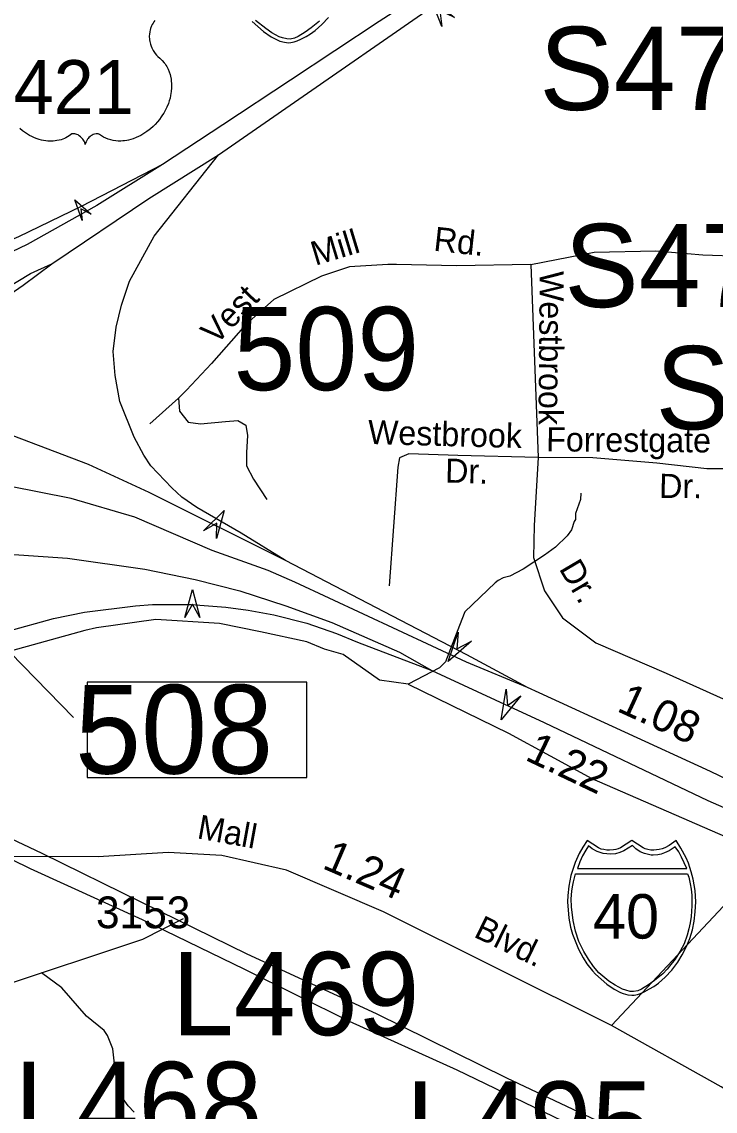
# Model space of a CAD drawing. Extents: x 1547597 to 1699558, y 810033 to 920809.
# Drawn here: x 1609043 to 1611776, y 845095 to 849388 of the extents above; entities that cross this region are included whole.
import ezdxf

# ---------------------------------------------------------------- set-up
doc = ezdxf.new("R2010")
doc.units = 0
for name, color, linetype in [('Exist Hydrographic Creek Single Shore', 7, 'Continuous'), ('Exist Hydrographic Misc Water Feature', 7, 'Continuous'), ('Exist Road Non-System Type 51', 7, 'Continuous'), ('Exist Road Non-System Type 51 Label', 7, 'Continuous'), ('Exist Road Primary Interstate Divided Center Attributed', 7, 'Continuous'), ('Exist Road Primary Interstate Mileage Hundredths English Label', 7, 'Continuous'), ('Exist Road Primary Interstate Ramp 1 Lane Attributed', 7, 'Continuous'), ('Exist Road Primary Interstate Shield CELL', 7, 'Continuous'), ('Exist Road Primary Interstate Shield Number Label', 7, 'Continuous'), ('Exist Road Primary Interstate Structure Cantilever Sign Attributed CELL', 7, 'Continuous'), ('Exist Road Primary Interstate Structure Cantilever Sign Number Label', 7, 'Continuous'), ('Exist Road Primary Interstate Structure Ovrhead Sign Attributed CELL', 7, 'Continuous'), ('Exist Road Primary Interstate Structure Ovrhead Sign Number Label', 7, 'Continuous'), ('Exist Road Primary Interstate Structure Standard Bridge Number Label', 7, 'Continuous'), ('Exist Road Primary US Divided Attributed', 7, 'Continuous'), ('Exist Road Primary US Shield CELL', 7, 'Continuous'), ('Exist Road Primary US Shield Number Label', 7, 'Continuous'), ('Exist Road Secondary Mileage Hundredths English Label', 7, 'Continuous'), ('Exist Road Secondary Structure Standard Bridge Number Label', 7, 'Continuous'), ('Exist Road Secondary Type 51 Label', 7, 'Continuous'), ('Exist Road Secondary Type 51 Number Label', 7, 'Continuous'), ('Exist Road Secondary Type 51 Undivided 4 Lane Attributed', 7, 'Continuous'), ('Exist Utilities Electrical Transmission Line', 7, 'Continuous')]:
    doc.layers.add(name, color=color, linetype=linetype)

msp = doc.modelspace()

# ---------------------------------------------------------------- linework, layer by layer
at = {"layer": 'Exist Hydrographic Creek Single Shore'}
for points in [[(1611246.6, 847530), (1611244.3, 847506), (1611225.6, 847450.3), (1611225.1, 847426.3), (1611219.1, 847418.4), (1611208.6, 847386.6), (1611192.3, 847362.8), (1611145.8, 847317.4), (1611103.3, 847286.1), (1611018.7, 847231.3), (1610966.3, 847204), (1610940.2, 847196.4), (1610920.1, 847186.6), (1610907.9, 847176.8), (1610788.9, 847063.2), (1610767.4, 847009.4), (1610712.7, 846865.3), (1610688.4, 846841.7), (1610566, 846777.2)], [(1610566, 846777.2), (1610961, 846584.5), (1611289.6, 846406.6), (1612056.2, 846072.2), (1612287.7, 846369.2), (1612438.7, 846458.1), (1612590.7, 846606), (1612844.7, 846952.1), (1612954.8, 847035.2), (1613264.7, 847173.3)], [(1610566, 846777.2), (1610453, 846793.2), (1610308.9, 846894.9), (1610236.4, 846915.1), (1610166, 846944.4), (1609983.2, 846984), (1609821.8, 847016.3), (1609571.5, 847032.4), (1609336.8, 846999.2), (1609290.9, 846989.4), (1608821.5, 846859.3), (1608481.2, 846771.3), (1607720.5, 846780.1), (1607526.9, 846727.3), (1607190.5, 846575.7), (1607012.5, 846597.3), (1606791.5, 846589.4)], [(1606395.7, 844663.6), (1606562.7, 844719.3), (1606867.7, 845021.6), (1607202.6, 845185.5), (1607520.7, 845297.3), (1607915.7, 845476.4), (1608523.7, 845477.2), (1608941.7, 845580.3), (1609519.7, 845772.1), (1609679.7, 845854.2)]]:
    msp.add_lwpolyline(points, dxfattribs=at)
at = {"layer": 'Exist Hydrographic Misc Water Feature'}
msp.add_lwpolyline([(1609486.3, 845091.1), (1609462.6, 845115.4), (1609439.1, 845147.7), (1609431.3, 845163.9), (1609412.4, 845244.1), (1609401.7, 845340.2), (1609380.5, 845392.5), (1609366.8, 845412.7), (1609297.6, 845469.7), (1609201.2, 845581), (1609120.1, 845639.5)], dxfattribs=at)
at = {"layer": 'Exist Road Non-System Type 51'}
for points in [[(1611048.3, 848432), (1611299.2, 848479.8), (1611542.2, 848485.9), (1611726.7, 848470.5), (1611880.5, 848464.4)], [(1610485.4, 848432), (1610334.7, 848422.8), (1610223.9, 848385.9), (1610036.3, 848293.5), (1609925.6, 848195), (1609790.2, 848041.1), (1609691.8, 847936.4), (1609661, 847905.6)], [(1611048.3, 848432), (1610756.1, 848425.9), (1610519.2, 848432), (1610485.4, 848432)], [(1611048.3, 848432), (1611078, 847671.6)], [(1609661, 847905.6), (1609547.2, 847804.1)], [(1609661, 847905.6), (1609664.1, 847853.3), (1609697.9, 847810.2), (1609747.2, 847804.1), (1609845.6, 847813.3), (1609894.8, 847816.4), (1609925.6, 847797.9), (1609931.7, 847757.9), (1609928.6, 847690.2), (1609928.6, 847637.8), (1609956.3, 847585.5), (1610008.6, 847505.5)], [(1611078, 847671.6), (1610761.5, 847679.1), (1610567.7, 847685.2), (1610530.8, 847669.8), (1610524.6, 847632.9), (1610490.8, 847165)], [(1611078, 847671.6), (1611062.6, 847403.7), (1611059.5, 847277.5), (1611102.6, 847145.2), (1611173.1, 847039.1), (1611305.4, 846940.6), (1611582.2, 846820.5), (1611911.4, 846672.8), (1612215.9, 846565)], [(1611875, 847626.7), (1611742.7, 847626.7), (1611545.8, 847648.3), (1611293.6, 847669.8), (1611078, 847671.6)], [(1611366.8, 845431.8), (1611828.1, 845924.3), (1612061.9, 846181.6)]]:
    msp.add_lwpolyline(points, dxfattribs=at)
at = {"layer": 'Exist Road Primary Interstate Divided Center Attributed'}
for points in [[(1609818, 848863.7), (1610951.8, 849650.5), (1611075.2, 849735.8), (1611208.1, 849832), (1611360.5, 849948.2), (1611508.2, 850064.4), (1611742.4, 850253.5), (1612088.1, 850529.5), (1612330.6, 850725.5)], [(1610880.9, 849686.6), (1610801.9, 849625.3), (1610654, 849520.7), (1610451.7, 849389.8), (1610101.9, 849158.9), (1609835, 848982.1), (1609597.4, 848825.8)], [(1609160.8, 848434.9), (1609543.6, 848692.4), (1609818, 848863.7)], [(1609597.4, 848825.8), (1609338.8, 848663.7), (1609064, 848510.1), (1608755.1, 848363), (1608523.3, 848239.8), (1608398.1, 848184.5), (1608235.8, 848106.3), (1608071.5, 848018.3), (1607971.8, 847958.6)], [(1608507.6, 847894.1), (1608577.1, 847968.7), (1608628.7, 848030.7), (1608682.9, 848079.4), (1608745.7, 848127.1), (1608859.3, 848220), (1609048.4, 848350.8), (1609160.8, 848434.9)], [(1611035.3, 846765.2), (1610795.8, 846864.2), (1610118.6, 847179.8), (1610014, 847225.8), (1609792.5, 847304.8), (1609487.9, 847435.5), (1609237.6, 847509.1), (1608991.2, 847558.7), (1608763.3, 847591.7), (1608603, 847605.2), (1608500.8, 847605.4), (1608391.6, 847601.3), (1608289.9, 847591.6), (1608209.9, 847577)], [(1607391.9, 846999.6), (1607538.3, 847060.1), (1607712.6, 847122.6), (1607907.2, 847179.3), (1608092, 847220.4), (1608274.9, 847254.6), (1608496.9, 847276.6), (1608631.8, 847286.4), (1608854.8, 847292.7), (1608937.9, 847292.7), (1609030.8, 847287.4), (1609223.4, 847273.7), (1609527.5, 847231.1), (1609726, 847190.8), (1609902.5, 847145.8), (1610082.9, 847086.7), (1610264.8, 847021.2), (1610531.7, 846904.5), (1610658.9, 846832.2)], [(1610658.9, 846832.2), (1610961.8, 846690.7), (1611101.2, 846626.2), (1611746, 846318.7), (1612061.9, 846181.6)], [(1612123.7, 846257), (1611757, 846433), (1611081.3, 846743.4), (1611035.3, 846765.2)]]:
    msp.add_lwpolyline(points, dxfattribs=at)
at = {"layer": 'Exist Road Primary Interstate Ramp 1 Lane Attributed'}
for points in [[(1610081.9, 847264.6), (1609906.9, 847372.7), (1609732.4, 847474.4), (1609673.2, 847515), (1609634.6, 847551.1), (1609551.9, 847638.9), (1609523.6, 847680.9), (1609485.5, 847751.3), (1609429.7, 847891.7), (1609411.1, 847994.3), (1609403.3, 848089.2), (1609414.1, 848185), (1609435.6, 848272), (1609467.9, 848365.9), (1609564.7, 848542.9), (1609818, 848863.7)], [(1610081.9, 847264.6), (1609544.6, 847533), (1609305.5, 847643.8), (1608910.9, 847793.1), (1608706.1, 847852.1), (1608604.4, 847878.5), (1608507.6, 847894.1)], [(1611035.3, 846765.2), (1610797.2, 846893.8), (1610081.9, 847264.6)], [(1607391.9, 846999.6), (1607516.1, 846956.1), (1607705.8, 846904.8), (1607792.8, 846883.8), (1607894.5, 846867.1), (1608005, 846856.4), (1608095.4, 846862.5), (1608309.7, 846862.5), (1608500.2, 846879.8), (1608828.4, 846941.2), (1608987.7, 846986.2), (1609167.7, 847036.1), (1609289.9, 847062), (1609490.3, 847086.9), (1609558.3, 847091.3), (1609709.9, 847091.1), (1609846.8, 847080.8), (1609934.3, 847069.8), (1610036.5, 847050.7), (1610166, 847018.7), (1610283.4, 846976.9), (1610365.5, 846943.7), (1610658.9, 846832.2)]]:
    msp.add_lwpolyline(points, dxfattribs=at)
at = {"layer": 'Exist Road Primary Interstate Shield CELL'}
for points in [[(1609950.3, 849389.2), (1609995.1, 849350), (1610025, 849329.6), (1610048.9, 849316.7), (1610060.2, 849312.4), (1610077.8, 849307.5), (1610093.9, 849305.7), (1610103.4, 849306.6), (1610116.1, 849309), (1610128.5, 849313.1), (1610142.6, 849319.3), (1610163.5, 849330.9), (1610180.2, 849340.7), (1610199.6, 849353.7), (1610225.7, 849377.4), (1610251.7, 849404.8)], [(1610215.9, 849390.3), (1610183.6, 849364.4), (1610160.1, 849346.9), (1610132, 849330.2), (1610117.6, 849323.9), (1610101, 849320.4), (1610087.3, 849321.3), (1610070.6, 849325.7), (1610057.2, 849329.4), (1610027.8, 849345.3), (1610003.9, 849361.3), (1609964.1, 849393.9)]]:
    msp.add_lwpolyline(points, dxfattribs=at)
for points in [[(1611446.9, 845551.4), (1611456.3, 845552.3), (1611469.1, 845554.8), (1611481.5, 845558.8), (1611495.6, 845565.1), (1611516.4, 845576.6), (1611533.2, 845586.4), (1611552.5, 845599.4), (1611578.6, 845623.1), (1611604.7, 845650.5), (1611627.7, 845681.6), (1611645.9, 845710.6), (1611662, 845743.7), (1611675.4, 845774.7), (1611686.1, 845810), (1611693.1, 845844.2), (1611696.7, 845879.9), (1611699.1, 845919.5), (1611696.4, 845964), (1611688.7, 846009.6), (1611681.4, 846037.9), (1611670.4, 846071.9), (1611661.4, 846093.6), (1611640.5, 846132), (1611621.8, 846161.6), (1611594.6, 846142.4), (1611576.8, 846133), (1611565.9, 846128.1), (1611554.8, 846125.9), (1611534.3, 846123.5), (1611521.4, 846124), (1611509.5, 846126.7), (1611499.3, 846128.9), (1611491.1, 846133), (1611446.9, 846161.6), (1611402.6, 846133), (1611393.3, 846128.7), (1611383.8, 846126.7), (1611374.6, 846124.2), (1611359.5, 846123.5), (1611347.9, 846123.8), (1611336.1, 846125.9), (1611326.7, 846127.9), (1611316.2, 846133), (1611271.1, 846161.6), (1611253.3, 846135.9), (1611238.9, 846110.5), (1611223.5, 846074.5), (1611214, 846046.7), (1611207.2, 846023.8), (1611198.8, 845981.9), (1611194.5, 845945.3), (1611193.7, 845919.5), (1611198.5, 845855), (1611205.5, 845820.6), (1611212.8, 845792.8), (1611236.6, 845732.8), (1611254.6, 845699.2), (1611270, 845675), (1611291.5, 845647.8), (1611303.2, 845634.9), (1611348, 845595.7), (1611378, 845575.3), (1611401.9, 845562.4), (1611413.1, 845558.1), (1611430.7, 845553.2)], [(1611276.4, 846140.8), (1611265.4, 846123.9), (1611252.8, 846101.1), (1611242.6, 846077.4), (1611232.3, 846051.2), (1611663.8, 846051.1), (1611653.8, 846073.5), (1611643, 846096), (1611631.8, 846116.6), (1611618, 846136.5), (1611593.8, 846121.3), (1611576.2, 846112.9), (1611562, 846108), (1611550.1, 846105.4), (1611531.5, 846103.9), (1611523.1, 846104.4), (1611497.2, 846110.2), (1611479.7, 846117.4), (1611463, 846128.6), (1611449.4, 846141.3), (1611415.2, 846120.6), (1611400.1, 846113.9), (1611382.6, 846109.5), (1611363.5, 846107.1), (1611334.1, 846110.3), (1611311, 846118.2), (1611291.2, 846128.6)], [(1611666.4, 846029.8), (1611671, 846017.6), (1611677.4, 845990.6), (1611680.7, 845969.7), (1611684.1, 845945.7), (1611682.9, 845904.6), (1611680.9, 845862), (1611677, 845836.8), (1611671.8, 845813.9), (1611664.6, 845788.4), (1611653.1, 845754.6), (1611637.2, 845725.9), (1611617.3, 845694.1), (1611595.8, 845666.2), (1611586.5, 845654.7), (1611568.8, 845636), (1611536.6, 845610.1), (1611513.1, 845592.6), (1611484.9, 845575.9), (1611470.6, 845569.6), (1611453.9, 845566.1), (1611440.2, 845567), (1611423.6, 845571.4), (1611410.1, 845575.1), (1611380.7, 845591), (1611356.8, 845607), (1611317.1, 845639.6), (1611295.6, 845664.7), (1611275.6, 845694.1), (1611257.7, 845724.2), (1611238.6, 845763.9), (1611225.2, 845803.8), (1611215.4, 845846.8), (1611208.8, 845899.5), (1611208, 845931.5), (1611210, 845962.4), (1611212.9, 845978.5), (1611216.9, 845998.6), (1611224.7, 846029.6)]]:
    msp.add_lwpolyline(points, close=True, dxfattribs=at)
at = {"layer": 'Exist Road Primary Interstate Structure Cantilever Sign Attributed CELL'}
for points in [[(1610697.9, 849369.4), (1610655.1, 849481), (1610747.9, 849405.8), (1610690.2, 849432.7)], [(1609685.4, 847039.9), (1609714.9, 847150.3), (1609744.5, 847039.9), (1609714.9, 847093.1)], [(1611009.3, 846731.6), (1610931.6, 846637.7), (1610951.9, 846757.9), (1610957, 846693.1)]]:
    msp.add_lwpolyline(points, close=True, dxfattribs=at)
at = {"layer": 'Exist Road Primary Interstate Structure Ovrhead Sign Attributed CELL'}
for points in [[(1609280.2, 848605.7), (1609252.1, 848686.3), (1609316.7, 848630.5), (1609276.1, 848651)], [(1609759.1, 847382), (1609841, 847461.7), (1609809.9, 847351.7), (1609811.8, 847412.6)], [(1610814.7, 846947.3), (1610723.2, 846866.7), (1610762.2, 846982.2), (1610757, 846917.5)]]:
    msp.add_lwpolyline(points, close=True, dxfattribs=at)
at = {"layer": 'Exist Road Primary Interstate Structure Standard Bridge Number Label'}
msp.add_line((1608408.9, 847506.4), (1609245.9, 846645.9), dxfattribs=at)
msp.add_lwpolyline([(1610166.4, 846785.1), (1609299.9, 846785.1), (1609299.9, 846409.5), (1610166.4, 846409.5)], close=True, dxfattribs=at)
at = {"layer": 'Exist Road Primary US Divided Attributed'}
for points in [[(1609597.4, 848825.8), (1609277.2, 848659.8), (1609029.8, 848541.4), (1608670.9, 848390.4), (1608590.7, 848364.9), (1608497.4, 848333.4), (1608341.4, 848280.4), (1608224.1, 848247.1), (1608078.4, 848199.2), (1607571.8, 848040.8), (1607380.2, 847987), (1607135.7, 847939.1), (1606868.8, 847890), (1606537.3, 847865.3)], [(1608330.6, 847921.5), (1608418.9, 847977.6), (1608608.3, 848089.2), (1608983.8, 848340), (1609077.7, 848396.7), (1609160.8, 848434.9)]]:
    msp.add_lwpolyline(points, dxfattribs=at)
at = {"layer": 'Exist Road Primary US Shield CELL'}
msp.add_lwpolyline([(1609567.1, 849393.6), (1609563.3, 849388.4), (1609560, 849383.2), (1609556.7, 849377.5), (1609554.3, 849372.6), (1609550.4, 849362.2), (1609548.5, 849355.7), (1609547.3, 849350.2), (1609545.8, 849338.7), (1609545.4, 849333.2), (1609545.4, 849327.8), (1609545.7, 849322.1), (1609546.2, 849316.7), (1609547.2, 849311), (1609548.1, 849305.9), (1609549.7, 849299.8), (1609552, 849292.6), (1609554.8, 849285.7), (1609560.7, 849274.6), (1609568.2, 849263.2), (1609573.6, 849256.8), (1609578.9, 849251.3), (1609586.9, 849244.6), (1609591.2, 849240.8), (1609596.1, 849235.9), (1609604.2, 849226.5), (1609607.4, 849222.1), (1609610.7, 849217.2), (1609613.8, 849212.1), (1609616.8, 849206.6), (1609619.2, 849201.8), (1609623.8, 849190.8), (1609627.1, 849180.1), (1609628.6, 849174.5), (1609631, 849161.9), (1609631.9, 849155.6), (1609632.9, 849143.3), (1609632.9, 849128.4), (1609631.8, 849114.3), (1609629.1, 849097.8), (1609626.9, 849087.9), (1609623.5, 849076.5), (1609620.3, 849066.5), (1609614.4, 849051.8), (1609609.2, 849041.2), (1609602.4, 849028.7), (1609597.8, 849021.2), (1609592.4, 849013.2), (1609585.6, 849003.9), (1609577.7, 848994), (1609568.2, 848983.6), (1609560.6, 848975.9), (1609550.5, 848967), (1609544.5, 848962), (1609535.8, 848955.4), (1609524, 848947.5), (1609512.3, 848940.8), (1609502.3, 848935.7), (1609493.5, 848931.9), (1609482.1, 848927.5), (1609463.1, 848922.3), (1609456.2, 848920.8), (1609448, 848919.6), (1609440.4, 848918.9), (1609432.9, 848918.4), (1609422.9, 848918.4), (1609412.9, 848919.2), (1609403.5, 848920.5), (1609393.7, 848922.6), (1609383.5, 848925.6), (1609374.2, 848929.3), (1609364.7, 848933.9), (1609348.8, 848943.9), (1609344.2, 848946.4), (1609341.7, 848947.1), (1609335.5, 848947.4), (1609329.7, 848946.1), (1609323.8, 848943.8), (1609320.2, 848941.9), (1609315.5, 848938.8), (1609311.8, 848935.9), (1609307.4, 848931.7), (1609304.4, 848928.2), (1609302.1, 848925.5), (1609297.6, 848918.4), (1609296, 848915.1), (1609294.3, 848910.7), (1609292.9, 848904.4), (1609290.8, 848912.4), (1609288.5, 848917.7), (1609285.8, 848922.3), (1609282.9, 848926.3), (1609278.4, 848931.5), (1609274.4, 848935.4), (1609269.5, 848939.3), (1609264.4, 848942.4), (1609260.2, 848944.5), (1609256.4, 848946), (1609251.8, 848947.1), (1609248, 848947.4), (1609244.9, 848947.4), (1609240.6, 848946.4), (1609234.8, 848942.2), (1609229.3, 848938.4), (1609223.3, 848934.7), (1609216.1, 848930.9), (1609210.9, 848928.4), (1609204.7, 848926), (1609197.4, 848923.6), (1609189.5, 848921.5), (1609181.4, 848919.9), (1609174.2, 848918.8), (1609166.6, 848918.1), (1609159.6, 848917.9), (1609152.4, 848918), (1609145.7, 848918.5), (1609137.8, 848919.2), (1609128.1, 848920.6), (1609120.1, 848922.4), (1609111.6, 848924.7), (1609102.8, 848927.5), (1609093.5, 848931), (1609081.8, 848936.1), (1609073.7, 848940.3), (1609060.8, 848947.7), (1609045.8, 848958.1), (1609034.4, 848967.3)], dxfattribs=at)
at = {"layer": 'Exist Road Secondary Type 51 Undivided 4 Lane Attributed'}
msp.add_lwpolyline([(1612615.5, 844613.7), (1612074.7, 845015.1), (1611799, 845190.3), (1611366.8, 845431.8), (1610467.7, 845880.2), (1610085.9, 846044.7), (1609831.3, 846103.1), (1609619.1, 846113.7), (1609343.4, 846097.7), (1607863.6, 846103.1), (1607386.9, 846148.3), (1607003.8, 846236.7), (1606952.2, 846249.5), (1606830.6, 846307.8), (1606684, 846415.4), (1606544.1, 846528.1)], dxfattribs=at)
at = {"layer": 'Exist Utilities Electrical Transmission Line'}
for points in [[(1606414.8, 848402.5), (1606538.4, 848250.7), (1606768.3, 848017.1), (1606954.8, 847808.4), (1607078.7, 847690.4), (1607312.4, 847433), (1607510.7, 847227.8), (1607703.2, 847021), (1607962.8, 846755), (1608139.7, 846576.3), (1608269.4, 846518.8), (1608703.7, 846308.3), (1609122.2, 846111.9), (1609516.8, 845917.8), (1609929.2, 845715.5), (1610439.1, 845479.9), (1610952.6, 845226.1), (1611495.9, 844970)], [(1606466.3, 848251.8), (1606706.1, 848008.2), (1606841.7, 847854.1), (1606979.2, 847710.1), (1607161.8, 847517.3), (1607277.7, 847387.4), (1607460.4, 847194.8), (1607637, 847000.1), (1607953.2, 846657.3), (1608082.8, 846515.2), (1608162.9, 846480.4), (1608571.7, 846298.2), (1609075.3, 846050.6), (1609517.7, 845850), (1609920.3, 845653.9), (1610332.6, 845449.6), (1610757.1, 845257.1), (1611173.7, 845056.7)]]:
    msp.add_lwpolyline(points, dxfattribs=at)

# ---------------------------------------------------------------- texts
at = {"layer": 'Exist Road Non-System Type 51 Label'}
for s, rotation, p in [('Mill', 16.8168, (1610199.3, 848426.5)), ('Rd.', 353.7514, (1610663.1, 848486.5)), ('Westbrook', 269.544, (1611084, 848406.7)), ('Vest', 45.9685, (1609807.7, 848111.7)), ('Westbrook', 358.4329, (1610405.9, 847724.6)), ('Forrestgate', 359.5943, (1611109.1, 847695.5)), ('Dr.', 358.4329, (1610710.2, 847572.5)), ('Dr.', 359.5943, (1611554.4, 847511.9)), ('Dr.', 300.5019, (1611158, 847233))]:
    msp.add_text(s, height=95, rotation=rotation, dxfattribs=at).set_placement(p)
at = {"layer": 'Exist Road Primary Interstate Mileage Hundredths English Label'}
for s, rotation, p in [('1.08', 335.3222, (1611383.5, 846673.4)), ('1.22', 334.5087, (1611021.7, 846481.1))]:
    msp.add_text(s, height=125, rotation=rotation, dxfattribs=at).set_placement(p)
at = {"layer": 'Exist Road Primary Interstate Shield Number Label'}
msp.add_text('40', height=175, dxfattribs=at).set_placement((1611294, 845775.1))
at = {"layer": 'Exist Road Primary Interstate Structure Cantilever Sign Number Label'}
for s, p in [('L469', (1609633.9, 845394.3)), ('L468', (1609014.6, 844961.2)), ('L495', (1610556, 844883.8))]:
    msp.add_text(s, height=328.08, dxfattribs=at).set_placement(p)
at = {"layer": 'Exist Road Primary Interstate Structure Ovrhead Sign Number Label'}
for s, p in [('S472', (1611082.7, 849040.7)), ('S471', (1611181.2, 848263.9)), ('S470', (1611540.5, 847782.3))]:
    msp.add_text(s, height=328.08, dxfattribs=at).set_placement(p)
at = {"layer": 'Exist Road Primary Interstate Structure Standard Bridge Number Label'}
msp.add_text('508', height=350, dxfattribs=at).set_placement((1609252.5, 846425.1))
at = {"layer": 'Exist Road Primary US Shield Number Label'}
msp.add_text('421', height=212.5, dxfattribs=at).set_placement((1609010.2, 849024.7))
at = {"layer": 'Exist Road Secondary Mileage Hundredths English Label'}
msp.add_text('1.24', height=125, rotation=336.6928, dxfattribs=at).set_placement((1610222.6, 846053.8))
at = {"layer": 'Exist Road Secondary Structure Standard Bridge Number Label'}
msp.add_text('509', height=328.08, dxfattribs=at).set_placement((1609876.9, 847936.5))
at = {"layer": 'Exist Road Secondary Type 51 Label'}
for s, rotation, p in [('Mall', 349.7036, (1609730.2, 846170.6)), ('Blvd.', 334.0784, (1610820, 845783.7))]:
    msp.add_text(s, height=95, rotation=rotation, dxfattribs=at).set_placement(p)
at = {"layer": 'Exist Road Secondary Type 51 Number Label'}
msp.add_text('3153', height=125, dxfattribs=at).set_placement((1609335.2, 845815.9))

doc.saveas('drawing.dxf')
